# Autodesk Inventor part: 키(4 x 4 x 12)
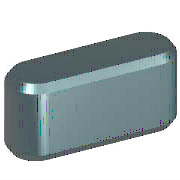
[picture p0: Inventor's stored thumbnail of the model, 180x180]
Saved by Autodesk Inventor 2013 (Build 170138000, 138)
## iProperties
IsCustomPart: 0
Created: 2009-02
Part Number: 키(4 x 4 x 12)
Material: 강, 연강
Description: 키 및 해당 키홈
Document SubType Name: Modeling
Standard: KS B 1311
Designer: KYOUNG IL JANG
Standards Organization: KS
Language: ko-KR
Size Designation: 4 x 4 x 12
Categories: <MemberInstance><Categories><Category DisplayName="샤프트 부품" InternalName="7f7aeb1f-a693-4053-b835-cee3144e0d98" Mnemonic="SHFT"><Category DisplayName="키" Interna
Density: 7.86 g/cm^3
Mass: 1.38739 g
Surface Area: 1.94869 cm^2
Volume: 0.176513 cm^3
Author: KYOUNG IL JANG
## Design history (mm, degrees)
workplane "Work Plane1"
workplane "Work Plane2"
sketch "스케치1"
  geometry: L1 (2, 2)-(10, 2); L2 (10, -2)-(2, -2); L3 (0, 9.4)-(0, -7.4) reference; L4 (-5, 0)-(30, 0) reference; L5 (12, 0)-(12, 7); A1 r 2 centre (2, 0) between (2, 2) and (2, -2); A2 r 2 centre (10, 0) between (10, -2) and (10, 2)
  constraints: 6 end point, 5 point on circle, 4 tangent, 3 point on line, 2 centre point, 1 horizontal, 1 parallel, 1 perpendicular
  dimensions: "d0" = 2 radius of A1 (= 0.5 x PB); "d13" = 2 radius of A2 (= 0.5 x PB); "d14" = 12 distance between parallel lines of L5 L3 (= NLG)
extrude "본체1" new body sketch "스케치1" taper "d3" = 0 deg; stored distance "d4" = 10
workplane "Work Plane3"
body "Solid1"
chamfer "모따기1" distance "d8" = 0.25 (= PHH); stored, may be unused: second distance "d9" = 0.25 (= PHH), angle "d15" = 45 deg
other parameters: "d1" = -2.5 (= -PNT), "d2" = 1.5 (= PH - PNT), "NLG" = 12 [user parameter; used in 3 equation terms], "PB" = 4 [user parameter; used in 2 equation terms], "PNT" = 2.5 [user parameter; used in 2 equation terms], "PH" = 4 [user parameter; used in 1 equation term], "PHH" = 0.25 [user parameter; used in 2 equation terms], "d10" = 0, "d16" = 0, "d17" = 0, "d18" = 0, "PLB2" = 12 (= NLG) [user parameter], "WDMAX" = 12 [user parameter], "PLB1" = 12 (= NLG) [user parameter], "RR" = 0.08 [user parameter], "PUEB" = 1.8 [user parameter]
